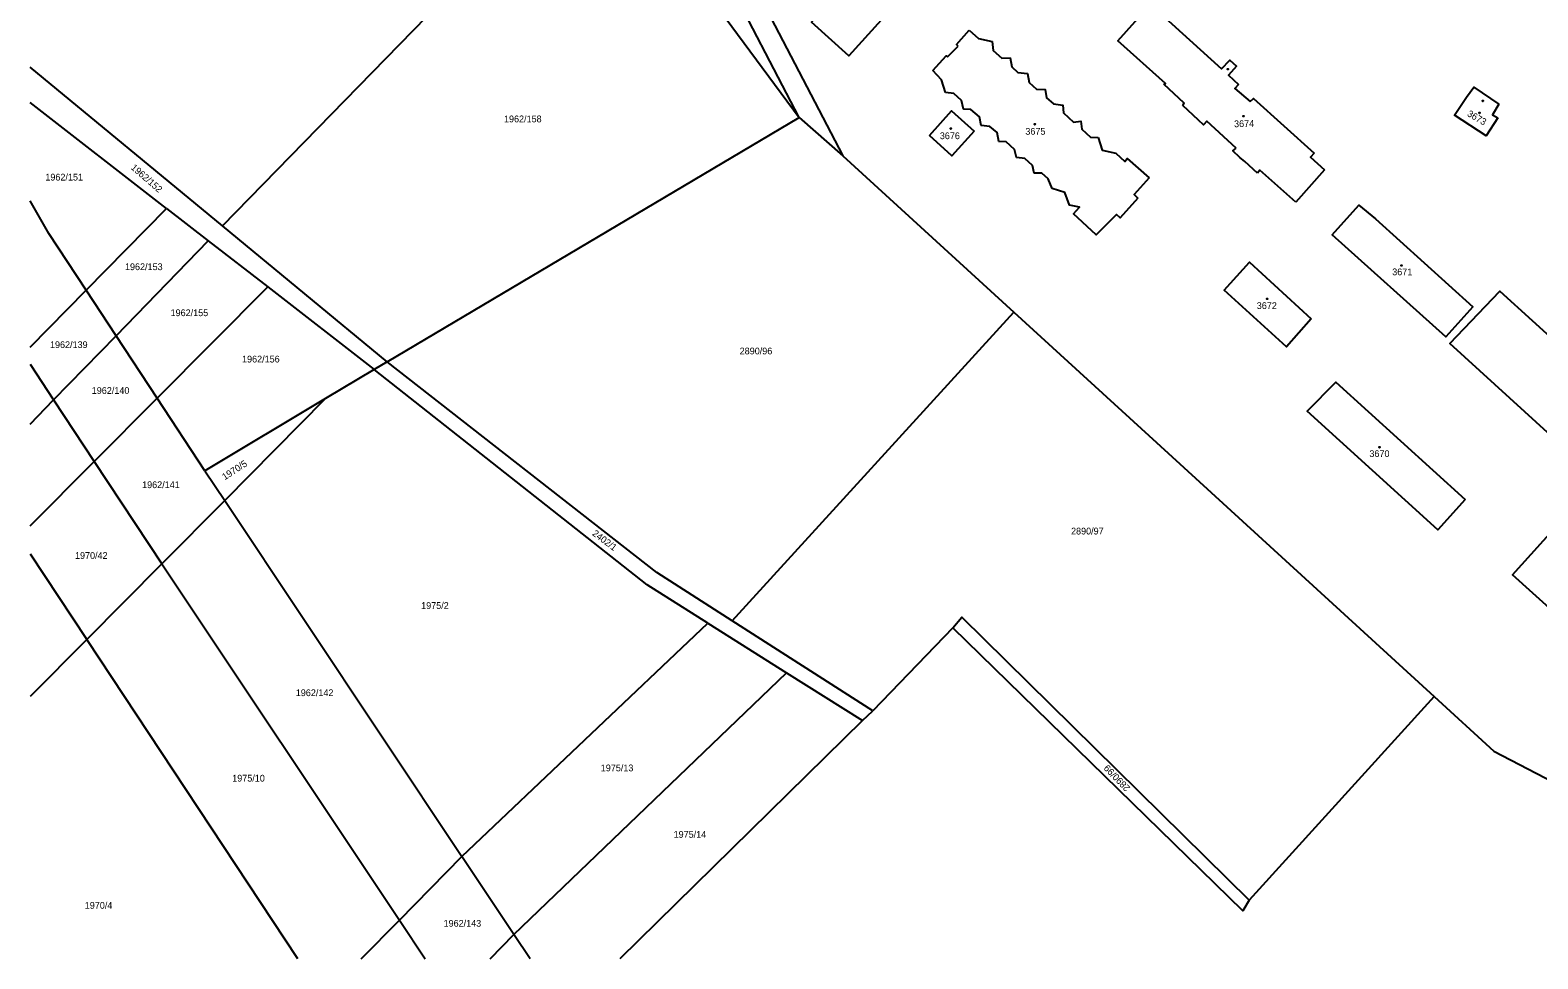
# Model space of a CAD drawing. Extents: x -667048 to -665920, y -1108425 to -1107247.
# Drawn here: x -667043.5 to -666663.6, y -1108425.1 to -1108191.2 of the extents above; entities that cross this region are included whole.
import ezdxf

# ---------------------------------------------------------------- set-up
doc = ezdxf.new("R2010")
doc.units = 0
for name, color, linetype in [('Default', 7, 'Continuous'), ('Hranice parcel', 7, 'Continuous'), ('Parcelní čísla', 7, 'Continuous'), ('Značky budov', 7, 'Continuous')]:
    doc.layers.add(name, color=color, linetype=linetype)

# ---------------------------------------------------------------- blocks, each defined once
blk = doc.blocks.new('4.021')
at = {"layer": 'Default'}
blk.add_circle((-7, 1), 175, dxfattribs=at)

msp = doc.modelspace()

# ---------------------------------------------------------------- linework, layer by layer
at = {"layer": 'Hranice parcel'}
for points in [[(-666994.96, -1108240.52), (-666912.59, -1108156.07)], [(-666867.93, -1108166.76), (-666838.73, -1108222.85)], [(-666827.35, -1108167.31), (-666826.35, -1108166.37), (-666816.89, -1108175.22), (-666837.22, -1108197.66), (-666846.59, -1108189.16), (-666827.35, -1108167.31)], [(-666849.72, -1108213.24), (-666868.77, -1108176.51)], [(-666872.92, -1108181.8), (-666849.72, -1108213.24)], [(-666757.86, -1108204.83), (-666757.48, -1108204.69), (-666769.47, -1108193.89), (-666762.11, -1108185.76), (-666761.22, -1108184.78), (-666743.33, -1108200.94), (-666741.27, -1108198.79), (-666739.6, -1108200.28), (-666741.61, -1108202.57), (-666739.03, -1108204.94)], [(-666809.7, -1108195.26), (-666810.13, -1108194.83), (-666806.91, -1108191.23)], [(-666806.91, -1108191.23), (-666804.58, -1108193.29), (-666801.11, -1108194.11)], [(-666801.11, -1108194.11), (-666800.89, -1108196.32), (-666798.65, -1108198.24), (-666796.61, -1108198.18), (-666796.16, -1108200.46), (-666794.64, -1108201.87), (-666792.19, -1108202.13), (-666791.8, -1108204.41), (-666789.9, -1108206.06), (-666787.74, -1108206.13), (-666787.44, -1108208.3), (-666785.65, -1108209.8), (-666783.29, -1108210.13), (-666783.1, -1108212.06), (-666780.66, -1108214.37), (-666778.81, -1108214.15), (-666778.54, -1108216.19), (-666776.3, -1108218.17), (-666774.39, -1108218.24)], [(-666816.02, -1108201.36), (-666812.68, -1108197.64), (-666812.34, -1108197.91)], [(-666812.34, -1108197.91), (-666809.7, -1108195.26)], [(-666994.96, -1108240.52), (-667043.46, -1108200.51)], [(-666812.85, -1108206.88), (-666813.84, -1108203.75), (-666816.02, -1108201.36)], [(-666753.12, -1108210.19), (-666752.71, -1108209.62), (-666757.86, -1108204.83)], [(-666739.03, -1108204.94), (-666739.94, -1108205.92), (-666736.15, -1108209.19)], [(-666673.7, -1108213.27), (-666676.64, -1108217.79), (-666684.63, -1108212.63), (-666681.61, -1108208.06), (-666679.81, -1108205.54), (-666673.49, -1108209.82)], [(-667009.1, -1108236.1), (-667043.46, -1108209.45)], [(-666786.02, -1108231.13), (-666787.02, -1108228.67), (-666788.59, -1108227.27), (-666790.53, -1108227.23), (-666790.97, -1108225.27), (-666792.91, -1108223.5), (-666794.96, -1108223.27), (-666795.45, -1108221.3), (-666797.58, -1108219.35), (-666799.42, -1108219.24), (-666799.88, -1108217.01), (-666801.72, -1108215.45), (-666803.9, -1108215.21), (-666804.32, -1108213.08), (-666806.48, -1108211.2), (-666808.35, -1108211.12), (-666808.83, -1108208.94), (-666810.78, -1108207.18), (-666812.85, -1108206.88)], [(-666736.15, -1108209.19), (-666735.29, -1108208.39), (-666720.02, -1108222.23)], [(-666953.49, -1108274.77), (-666849.72, -1108213.24)], [(-666849.72, -1108213.24), (-666838.73, -1108222.85)], [(-666816.93, -1108217.73), (-666811.34, -1108211.5), (-666805.68, -1108216.63)], [(-666739.67, -1108220.9), (-666747, -1108214.14), (-666747.88, -1108215.07), (-666749.17, -1108213.88), (-666753.12, -1108210.19)], [(-666673.49, -1108209.82), (-666675.1, -1108212.51), (-666673.7, -1108213.27)], [(-666805.68, -1108216.63), (-666811.29, -1108222.86), (-666816.93, -1108217.73)], [(-666774.39, -1108218.24), (-666773.36, -1108221.45), (-666769.96, -1108222.22), (-666767.73, -1108224.26), (-666767.07, -1108223.54), (-666761.55, -1108228.45)], [(-666738.73, -1108223.3), (-666740.45, -1108221.64), (-666739.67, -1108220.9)], [(-666838.73, -1108222.85), (-666795.66, -1108262.22)], [(-666734.27, -1108227.22), (-666737.5, -1108224.3), (-666738.73, -1108223.3)], [(-666720.02, -1108222.23), (-666720.89, -1108223.19), (-666717.42, -1108226.41)], [(-666761.55, -1108228.45), (-666765.37, -1108232.61), (-666764.44, -1108233.5)], [(-666724.62, -1108234.53), (-666733.64, -1108226.5), (-666734.27, -1108227.22)], [(-666717.42, -1108226.41), (-666724.62, -1108234.53)], [(-666764.44, -1108233.5), (-666768.85, -1108238.52), (-666769.82, -1108237.63), (-666774.94, -1108242.75), (-666780.63, -1108237.48), (-666779.14, -1108235.83), (-666781.66, -1108235.29), (-666782.84, -1108232.13), (-666786.02, -1108231.13)], [(-667029.36, -1108256.72), (-667038.77, -1108242.42), (-667043.46, -1108234.17)], [(-667029.36, -1108256.72), (-667009.1, -1108236.1)], [(-667009.1, -1108236.1), (-666998.6, -1108244.25)], [(-666704.51, -1108238.77), (-666680.04, -1108260.88), (-666686.83, -1108268.46), (-666715.47, -1108242.79), (-666708.73, -1108235.29), (-666704.51, -1108238.77)], [(-666953.49, -1108274.77), (-666994.96, -1108240.52)], [(-667021.83, -1108268.17), (-666998.6, -1108244.25)], [(-666998.6, -1108244.25), (-666983.58, -1108255.9)], [(-666720.71, -1108263.89), (-666726.94, -1108270.99), (-666742.65, -1108256.72), (-666736.26, -1108249.68), (-666720.71, -1108263.89)], [(-667043.46, -1108271.07), (-667029.36, -1108256.72)], [(-667021.83, -1108268.17), (-667029.36, -1108256.72)], [(-667011.46, -1108283.92), (-666983.58, -1108255.9)], [(-666983.58, -1108255.9), (-666956.76, -1108276.71)], [(-666632.48, -1108293.93), (-666645.17, -1108307.13), (-666685.8, -1108270.11), (-666673.21, -1108256.96), (-666632.48, -1108293.93)], [(-666866.6, -1108339.99), (-666795.66, -1108262.22)], [(-666795.66, -1108262.22), (-666756.74, -1108297.79), (-666689.78, -1108359.08)], [(-667037.54, -1108284.34), (-667021.83, -1108268.17)], [(-667011.46, -1108283.92), (-667021.83, -1108268.17)], [(-667043.46, -1108275.36), (-667037.54, -1108284.34)], [(-666956.76, -1108276.71), (-666969.06, -1108284)], [(-666953.49, -1108274.77), (-666956.76, -1108276.71)], [(-666872.78, -1108340.54), (-666888.06, -1108330.91), (-666956.76, -1108276.71)], [(-666866.6, -1108339.99), (-666885.57, -1108327.84), (-666953.49, -1108274.77)], [(-666681.99, -1108309.4), (-666688.87, -1108317.04), (-666721.75, -1108287.2), (-666714.54, -1108279.87), (-666681.99, -1108309.4)], [(-667043.46, -1108290.43), (-667037.54, -1108284.34)], [(-667037.54, -1108284.34), (-667027.32, -1108299.86)], [(-667027.32, -1108299.86), (-667011.46, -1108283.92)], [(-666999.42, -1108302.22), (-667011.46, -1108283.92)], [(-666969.06, -1108284), (-666999.42, -1108302.22)], [(-666994.44, -1108309.7), (-666969.06, -1108284)], [(-667043.46, -1108316.07), (-667027.32, -1108299.86)], [(-667027.32, -1108299.86), (-667010.32, -1108325.66)], [(-666999.42, -1108302.22), (-666994.44, -1108309.7)], [(-667010.32, -1108325.66), (-666994.44, -1108309.7)], [(-666994.44, -1108309.7), (-666934.72, -1108399.33)], [(-666657.55, -1108314.53), (-666598.42, -1108367.68), (-666611.23, -1108381.36), (-666670.05, -1108328.38), (-666657.55, -1108314.53)], [(-667043.46, -1108323.11), (-667029.18, -1108344.7)], [(-667029.18, -1108344.7), (-667010.32, -1108325.66)], [(-667010.32, -1108325.66), (-666950.44, -1108415.35)], [(-666934.72, -1108399.33), (-666872.78, -1108340.54)], [(-666872.78, -1108340.54), (-666852.91, -1108353.06)], [(-666831.19, -1108362.68), (-666866.6, -1108339.99)], [(-666811.04, -1108341.74), (-666831.19, -1108362.68)], [(-666811.04, -1108341.74), (-666808.79, -1108339.08), (-666736.34, -1108410.34)], [(-666736.34, -1108410.34), (-666737.97, -1108413), (-666811.04, -1108341.74)], [(-667029.18, -1108344.7), (-667043.46, -1108359.06)], [(-666976.01, -1108425.13), (-667029.18, -1108344.7)], [(-666921.64, -1108418.96), (-666852.91, -1108353.06)], [(-666852.91, -1108353.06), (-666833.78, -1108365.12)], [(-666689.78, -1108359.08), (-666736.34, -1108410.34)], [(-666689.78, -1108359.08), (-666674.75, -1108372.83), (-666659.73, -1108380.63)], [(-666833.78, -1108365.12), (-666894.92, -1108425.13)], [(-666833.78, -1108365.12), (-666831.19, -1108362.68)], [(-666950.44, -1108415.35), (-666934.72, -1108399.33)], [(-666921.64, -1108418.96), (-666934.72, -1108399.33)], [(-666960.05, -1108425.13), (-666950.44, -1108415.35)], [(-666950.44, -1108415.35), (-666943.91, -1108425.13)], [(-666927.58, -1108425.13), (-666921.64, -1108418.96)], [(-666917.53, -1108425.13), (-666921.64, -1108418.96)]]:
    msp.add_lwpolyline(points, dxfattribs=at)

# ---------------------------------------------------------------- block references
at = {"layer": 'Značky budov', "xscale": 0.0006700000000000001, "yscale": 0.0006700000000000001}
for p in [(-666741.76, -1108201.04), (-666677.51, -1108209.05), (-666737.76, -1108212.88), (-666678.34, -1108212.06), (-666811.49, -1108216), (-666790.33, -1108214.93), (-666697.95, -1108250.49), (-666731.81, -1108258.89), (-666703.56, -1108296.28)]:
    msp.add_blockref('4.021', p, dxfattribs=at)

# ---------------------------------------------------------------- texts
at = {"layer": 'Parcelní čísla'}
for s, p in [('1962/158', (-666924.09, -1108214.42)), ('3676', (-666814.3, -1108218.67)), ('3675', (-666792.75, -1108217.56)), ('1962/151', (-667039.63, -1108229.09)), ('1962/153', (-667019.57, -1108251.66)), ('3671', (-666700.33, -1108252.95)), ('1962/155', (-667008.08, -1108263.25)), ('3672', (-666734.45, -1108261.45)), ('1962/139', (-667038.46, -1108271.29)), ('1962/156', (-666990.08, -1108274.92)), ('2890/96', (-666864.72, -1108272.88)), ('1962/140', (-667027.94, -1108282.83)), ('3670', (-666706.08, -1108298.74)), ('1962/141', (-667015.25, -1108306.57)), ('2890/97', (-666781.24, -1108318.24)), ('1970/42', (-667032.16, -1108324.39)), ('1975/2', (-666944.96, -1108336.99)), ('1962/142', (-666976.54, -1108358.96)), ('1975/13', (-666899.71, -1108377.89)), ('1975/10', (-666992.55, -1108380.48)), ('1975/14', (-666881.36, -1108394.64)), ('1970/4', (-667029.7, -1108412.52)), ('1962/143', (-666939.31, -1108417.03))]:
    msp.add_text(s, height=1.7, dxfattribs=at).set_placement(p)
for s, rotation, p in [('3673', 330, (-666681.61, -1108212.73)), ('3674', 1, (-666740.16, -1108215.66)), ('1962/152', 319, (-667018.23, -1108226.05)), ('1970/5', 33, (-666994.43, -1108304.62)), ('2402/1', 323, (-666902, -1108318.3)), ('2890/99', 134, (-666766.22, -1108381.98))]:
    msp.add_text(s, height=1.7, rotation=rotation, dxfattribs=at).set_placement(p)

doc.saveas('drawing.dxf')
